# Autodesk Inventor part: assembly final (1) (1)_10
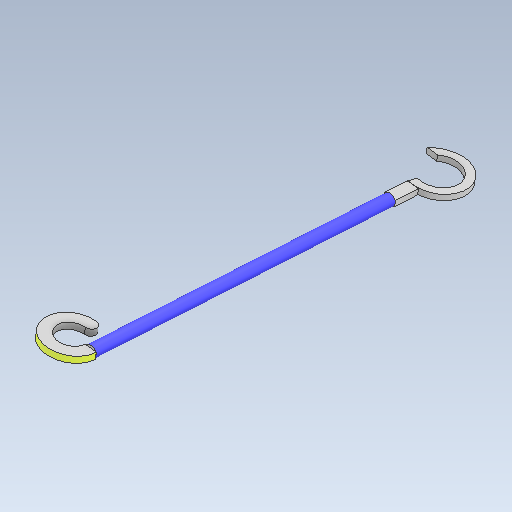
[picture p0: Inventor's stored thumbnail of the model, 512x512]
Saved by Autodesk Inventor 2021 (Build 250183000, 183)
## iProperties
Created: 2021-07
Part Number: assembly final (1) (1)_10
Material: Generic
Document SubType Name: Modeling
Designer: TARUN
Density: 1 g/cm^3
Appearance: Default
Author: TARUN
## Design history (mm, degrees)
feature "Base1"
body "Solid1"
